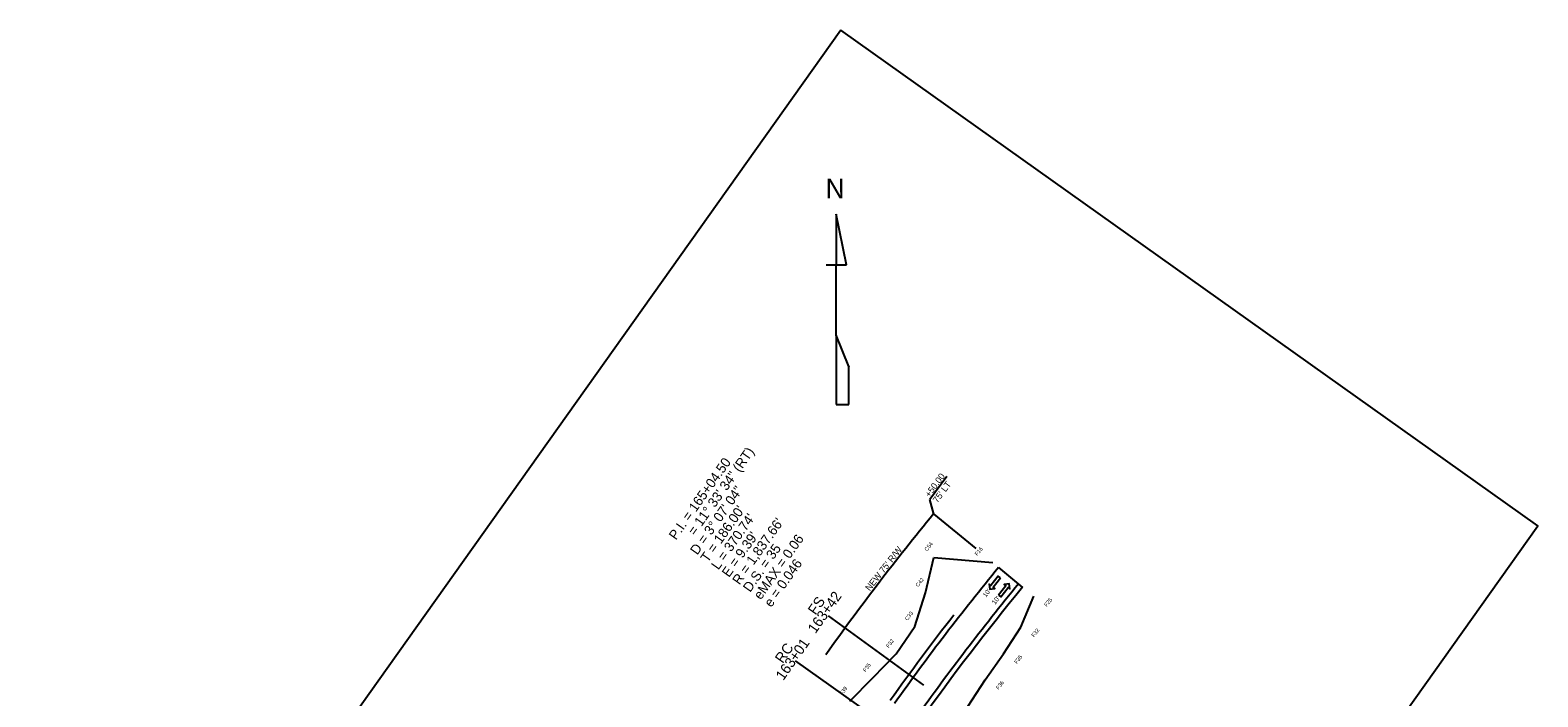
# Model space of a CAD drawing. Extents: x 1775013 to 1776177, y 1129170 to 1130432.
# Drawn here: x 1775013 to 1776177, y 1129918 to 1130432 of the extents above; entities that cross this region are included whole.
import ezdxf

# ---------------------------------------------------------------- set-up
doc = ezdxf.new("R2010")
doc.units = 0
for name, color, linetype in [('RD_EX_Misc', 7, 'Continuous'), ('RD_HC_Data', 7, 'Continuous'), ('RD_HC_Data_Tic', 7, 'Continuous'), ('RD_PD_CstnLmt', 7, 'Continuous'), ('RD_PD_CstnLmt_TX', 7, 'Continuous'), ('RD_PD_Final_TrvlWay', 7, 'Continuous'), ('RD_PD_Final_TX', 7, 'Continuous'), ('RD_PD_GR', 7, 'Continuous'), ('RD_PD_RW', 7, 'Continuous'), ('RD_PD_RW_TX', 7, 'Continuous'), ('RD_SHT_TX', 7, 'Continuous'), ('RD_Sketch2', 7, 'Continuous'), ('RD_Sketch8', 7, 'Continuous')]:
    doc.layers.add(name, color=color, linetype=linetype)

msp = doc.modelspace()

# ---------------------------------------------------------------- linework, layer by layer
at = {"layer": 'RD_EX_Misc'}
for p, q in [((1775643.5, 1130251.1), (1775635.6, 1130290.3)), ((1775635.6, 1130290.3), (1775635.6, 1130290.3)), ((1775635.6, 1130290.3), (1775635.6, 1130251.1)), ((1775627.8, 1130251.1), (1775635.6, 1130251.1)), ((1775635.6, 1130196.7), (1775635.6, 1130251.1)), ((1775635.6, 1130251.1), (1775643.5, 1130251.1)), ((1775643.5, 1130251.1), (1775643.5, 1130251.6)), ((1775645.4, 1130172.7), (1775635.6, 1130196.7)), ((1775635.6, 1130196.7), (1775635.6, 1130143.3)), ((1775645.4, 1130143.3), (1775645.4, 1130173)), ((1775645.4, 1130173), (1775645.4, 1130172.7)), ((1775635.6, 1130143.3), (1775645.4, 1130143.3))]:
    msp.add_line(p, q, dxfattribs=at)
at = {"layer": 'RD_HC_Data_Tic'}
msp.add_line((1775646.2, 1129975.8), (1775646.2, 1129975.8), dxfattribs=at)
at = {"layer": 'RD_PD_CstnLmt'}
for p, q in [((1775704.5, 1129997.9), (1775711.1, 1130025.3)), ((1775711.1, 1130025.3), (1775756.4, 1130021.3)), ((1775696.3, 1129972), (1775704.5, 1129997.9)), ((1775778.2, 1129971.6), (1775788.1, 1129995.3)), ((1775681.8, 1129951), (1775696.3, 1129972)), ((1775764.8, 1129950.9), (1775778.2, 1129971.6)), ((1775664, 1129932.5), (1775681.8, 1129951)), ((1775750.6, 1129930.9), (1775764.8, 1129950.9)), ((1775646.1, 1129914.5), (1775664, 1129932.5)), ((1775737.2, 1129910.3), (1775750.6, 1129930.9))]:
    msp.add_line(p, q, dxfattribs=at)
at = {"layer": 'RD_PD_Final_TrvlWay'}
msp.add_line((1775779.6, 1130002.2), (1775761.1, 1130017.5), dxfattribs=at)
for radius in [1847.7, 1827.7]:
    msp.add_arc((1777187.3, 1128843), radius, 140.5283, 144.6285, dxfattribs=at)
at = {"layer": 'RD_PD_Final_TX'}
for points in [[(1775762.5, 1130009.5), (1775760.6, 1130010.9), (1775754.9, 1130003.7), (1775753.7, 1130004.7), (1775754.1, 1130000.8), (1775758.1, 1130001.2), (1775756.8, 1130002.3)], [(1775760.9, 1129996.3), (1775762.8, 1129994.8), (1775768.4, 1130002), (1775769.7, 1130001), (1775769.2, 1130005), (1775765.3, 1130004.5), (1775766.5, 1130003.5)]]:
    msp.add_lwpolyline(points, close=True, dxfattribs=at)
at = {"layer": 'RD_PD_GR'}
for radius, start in [(1823.7, 140.5283), (1851.7, 142.0872)]:
    msp.add_arc((1777187.3, 1128843), radius, start, 144.6285, dxfattribs=at)
at = {"layer": 'RD_PD_RW'}
msp.add_line((1775710.9, 1130058.8), (1775743.3, 1130032.1), dxfattribs=at)
msp.add_arc((1777187.3, 1128843), 1912.7, 140.5283, 144.6285, dxfattribs=at)
at = {"layer": 'RD_PD_RW_TX'}
for p in [(1775721, 1130087.7), (1775710.9, 1130058.8)]:
    msp.add_line(p, (1775708, 1130069.9), dxfattribs=at)
at = {"layer": 'RD_Sketch2'}
msp.add_lwpolyline([(1775639.3, 1130432.2), (1775013.5, 1129552), (1775551.4, 1129169.5), (1776177.2, 1130049.7)], close=True, dxfattribs=at)
at = {"layer": 'RD_Sketch8'}
for p, q in [((1775703.2, 1129926.6), (1775629.6, 1129980.3)), ((1775678.8, 1129892.5), (1775604.2, 1129945.5))]:
    msp.add_line(p, q, dxfattribs=at)

# ---------------------------------------------------------------- texts
at = {"layer": 'RD_EX_Misc'}
msp.add_text('N', height=15, dxfattribs=at).set_placement((1775627.5, 1130302.5))
at = {"layer": 'RD_HC_Data'}
for s, p in [('P.I. = 165+04.50', (1775512, 1130038.2)), ('    = 11%%d 33\' 34" (RT)', (1775520.2, 1130032.5)), ('D = 3%%d 07\' 04"', (1775528.4, 1130026.7)), ("T = 186.00'", (1775536.5, 1130020.9)), ("L = 370.74'", (1775544.7, 1130015.2)), ("R = 1,837.66'", (1775561, 1130003.6)), ("E = 9.39'", (1775552.9, 1130009.4)), ('eMAX = 0.06', (1775577.4, 1129992.1)), ('D.S. = 35', (1775569.2, 1129997.9)), ('e = 0.046', (1775585.5, 1129986.3))]:
    msp.add_text(s, height=7.5, rotation=54.7709, dxfattribs=at).set_placement(p)
at = {"layer": 'RD_PD_CstnLmt_TX'}
for s, rotation, p in [('C54', 51.3077, (1775705.7, 1130029.7)), ('F16', 50.5283, (1775744.5, 1130026.3)), ('C42', 52.0872, (1775698.9, 1130002.2)), ('F25', 50.5283, (1775798.1, 1129987)), ('C33', 52.8667, (1775690.7, 1129976.2)), ('F32', 51.3077, (1775788.3, 1129963.5)), ('F32', 53.6462, (1775676.2, 1129955.2)), ('F35', 52.0872, (1775775.1, 1129942.9)), ('F35', 54.4256, (1775658.4, 1129936.6)), ('F39', 54.6285, (1775640.3, 1129918.5)), ('F36', 52.8667, (1775761, 1129923))]:
    msp.add_text(s, height=3, rotation=rotation, dxfattribs=at).set_placement(p)
at = {"layer": 'RD_PD_RW_TX'}
for s, rotation, p in [('+50.00', 53.7139, (1775707.7, 1130071.3)), ("75' LT", 53.7139, (1775713.8, 1130066.9)), ("NEW 75' R/W", 51.7172, (1775661.5, 1129999))]:
    msp.add_text(s, height=5, rotation=rotation, dxfattribs=at).set_placement(p)
at = {"layer": 'RD_SHT_TX'}
for p in [(1775751.2, 1129994.2), (1775758.3, 1129988.6)]:
    msp.add_text("10'", height=3.6, rotation=52.6341, dxfattribs=at).set_placement(p)
at = {"layer": 'RD_Sketch8'}
for s, p in [('FS', (1775619.7, 1129980.3)), ('163+42', (1775619.6, 1129966)), ('RC', (1775594.3, 1129943)), ('163+01', (1775594.8, 1129929.8))]:
    msp.add_text(s, height=8, rotation=54.9501, dxfattribs=at).set_placement(p)

doc.saveas('drawing.dxf')
